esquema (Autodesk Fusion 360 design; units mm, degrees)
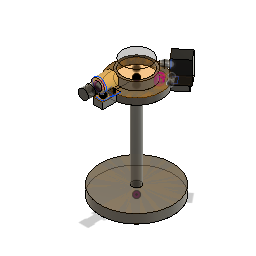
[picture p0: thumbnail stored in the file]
sketch "Sketch1" plane through (0, 0, 0) normal (0, 1, 0) x axis (1, 0, 0)
  circle C1 centre (0, 0) radius 40
  dimension "d1" diameter C1 = 80
extrude "Extrude1" new body sketch "Sketch1" along normal blind 10
sketch "Sketch2" plane through (0, 10, 0) normal (0, 1, 0) x axis (-1, 0, 0)
  circle C1 centre (0, 0) radius 40
  circle C2 centre (0, 0) radius 5
  dimension "d4" diameter C2 = 10
extrude "Extrude2" add sketch "Sketch2" profile of C2 along normal blind 95
sketch "Sketch3" plane through (0, 105, 0) normal (0, 1, 0) x axis (-1, 0, 0)
  circle C1 centre (0, 0) radius 5
  circle C2 centre (0, 0) radius 27.5
  dimension "d7" diameter C2 = 55
extrude "Extrude3" new body sketch "Sketch3" along normal blind 7
extrude "Extrude4" add of existing geometry blind 7
sketch "Sketch4"
sketch "Sketch5" plane through (0, 112, 0) normal (0, 1, 0) x axis (-1, 0, 0)
  dimension "d12" = 10
extrude "Extrude5" add sketch "Sketch5" against normal blind 7
extrude "Extrude6" add of existing geometry blind 10
sketch "Sketch6" plane through (0, 112, 0) normal (0, 1, 0) x axis (-1, 0, 0)
  dimension "d22" = 10
extrude "Extrude7" add sketch "Sketch6" against normal blind 7
extrude "Extrude8" add of existing geometry blind 10
sketch "Sketch7" plane through (0, 112, 0) normal (0, 1, 0) x axis (-1, 0, 0)
extrude "Extrude9" add sketch "Sketch7" along normal blind 6
sketch "Sketch8" plane through (0, 0, 41) normal (0, 0, 1) x axis (1, 0, 0)
  dimension "d29" = 15
extrude "Extrude10" new body sketch "Sketch8" against normal blind 14
extrude "Extrude11" add of existing geometry blind 2
sketch "Sketch9" plane through (0, 0, 41) normal (0, 0, 1) x axis (1, 0, 0)
extrude "Extrude12" add sketch "Sketch9" against normal blind 12
sketch "Sketch10" plane through (0, 0, 43) normal (0, 0, 1) x axis (1, 0, 0)
  circle C1 centre (0, 125.5) radius 7.5
  circle C2 centre (0, 125.5) radius 4.5
  dimension "d36" diameter C2 = 9
extrude "Extrude13" add sketch "Sketch10" profile of C2 along normal blind 8
sketch "Sketch11" plane through (0, 0, 51) normal (0, 0, 1) x axis (1, 0, 0)
  circle C1 centre (0, 125.5) radius 4.5
  circle C2 centre (0, 125.5) radius 5.5
  dimension "d39" diameter C2 = 11
extrude "Extrude14" add sketch "Sketch11" along normal blind 8
sketch "Sketch12" plane through (0, 112, 0) normal (0, 1, 0) x axis (-1, 0, 0)
  dimension "d43" = 2
extrude "Extrude15" add sketch "Sketch12" along normal blind 25
sketch "Sketch13" plane through (21.0491, 0, -16.976) normal (-0.7784, 0, 0.6278) x axis (0.6278, 0, 0.7784)
  dimension "d46" = 7
extrude "Extrude16" add sketch "Sketch13" along normal blind 5
sketch "Sketch14" plane through (17.1571, 0, -13.8371) normal (-0.7784, 0, 0.6278) x axis (0.6278, 0, 0.7784)
  circle C1 centre (0, 127) radius 3.5
  circle C2 centre (0, 127) radius 2.5
  dimension "d49" diameter C2 = 5
extrude "Extrude17" add sketch "Sketch14" profile of C2 along normal blind 4
sketch "Sketch15" plane through (0, 112, 0) normal (0, 1, 0) x axis (-1, 0, 0)
extrude "Extrude18" add sketch "Sketch15" along normal blind 9
sketch "Sketch16" plane through (0, 121, 0) normal (0, 1, 0) x axis (-1, 0, 0)
  circle C1 centre (0, 0) radius 18.0416
  circle C2 centre (0, 0) radius 15.5
  dimension "d54" diameter C2 = 31
extrude "Extrude19" add sketch "Sketch16" profile of C2 along normal blind 10
sketch "Sketch17"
